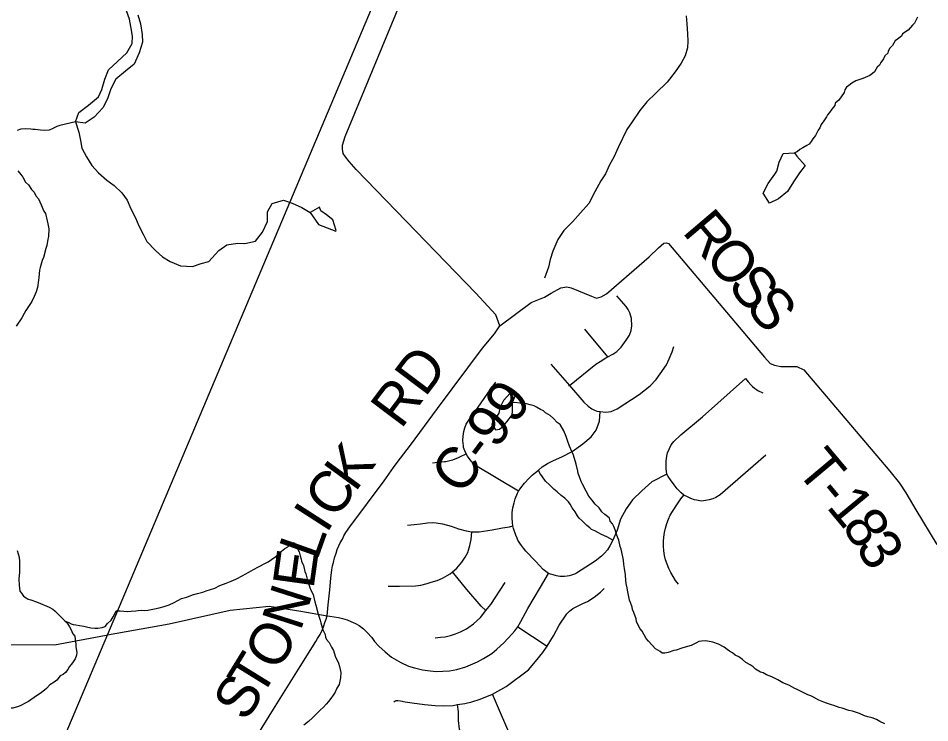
# Model space of a CAD drawing. Extents: x 0 to 34, y 0 to 22.
# Drawn here: x 8.015 to 8.641, y 16.311 to 16.795 of the extents above; entities that cross this region are included whole.
import ezdxf

# ---------------------------------------------------------------- set-up
doc = ezdxf.new("R2010")
doc.units = 0
for name, color, linetype in [('GM_X_Corporation', 7, 'Continuous'), ('GM_X_County_Road', 7, 'Continuous'), ('GM_X_County_Road_Text', 7, 'Continuous'), ('GM_X_Minor_Lake', 7, 'Continuous'), ('GM_X_Minor_River', 7, 'Continuous'), ('GM_X_Township', 7, 'Continuous'), ('GM_X_Township_Road', 7, 'Continuous'), ('GM_X_Township_Road_Text', 7, 'Continuous')]:
    doc.layers.add(name, color=color, linetype=linetype)

msp = doc.modelspace()

# ---------------------------------------------------------------- linework, layer by layer
at = {"layer": 'GM_X_Corporation'}
msp.add_lwpolyline([(8.48388, 17.33901), (8.07623, 16.37167), (8.03576, 16.27564)], dxfattribs=at)
at = {"layer": 'GM_X_County_Road'}
msp.add_line((8.19034, 16.32044), (8.2086, 16.34978), dxfattribs=at)
for points in [[(8.34554, 16.58365), (8.34282, 16.59136), (8.32915, 16.60605), (8.2471, 16.69119), (8.24218, 16.69661), (8.23968, 16.69986), (8.2381, 16.70219), (8.2376, 16.70502), (8.23768, 16.70769), (8.23951, 16.71369), (8.3129, 16.89147)], [(8.23054, 16.41746), (8.23076, 16.4188), (8.23138, 16.42121), (8.23219, 16.42433), (8.23326, 16.42763), (8.23406, 16.43004), (8.23513, 16.43254), (8.23593, 16.43459), (8.23754, 16.43727), (8.23861, 16.43941), (8.23986, 16.44164), (8.24262, 16.44556), (8.26629, 16.4772), (8.27271, 16.48647), (8.27521, 16.48977), (8.28428, 16.50168), (8.30293, 16.52684), (8.33385, 16.56838), (8.34208, 16.57812), (8.34554, 16.58365)], [(8.2271, 16.38459), (8.2277, 16.39196), (8.22898, 16.40234), (8.2296, 16.41046), (8.23031, 16.41612), (8.23054, 16.41746)], [(8.2086, 16.34978), (8.21929, 16.36697), (8.2205, 16.36889), (8.2222, 16.37174), (8.2238, 16.37522), (8.22478, 16.37772), (8.22559, 16.37986), (8.22634, 16.38222), (8.2271, 16.38459)], [(8.15853, 16.26881), (8.1597, 16.27071), (8.17295, 16.29239), (8.17469, 16.29529), (8.19034, 16.32044)]]:
    msp.add_lwpolyline(points, dxfattribs=at)
at = {"layer": 'GM_X_Minor_Lake'}
for points in [[(8.54809, 16.70243), (8.5496, 16.70026), (8.55519, 16.69389), (8.5513, 16.68883), (8.54739, 16.68263), (8.54328, 16.67605), (8.5371, 16.67102), (8.53077, 16.6679), (8.52652, 16.67482), (8.52986, 16.68141), (8.53454, 16.68779)], [(8.53454, 16.68779), (8.53591, 16.68986), (8.53735, 16.69611), (8.54012, 16.70214), (8.54809, 16.70243)], [(8.22271, 16.66264), (8.2218, 16.66513), (8.21546, 16.66163)], [(8.21546, 16.66163), (8.22122, 16.65335), (8.23312, 16.64877), (8.23332, 16.64915), (8.23097, 16.6566), (8.22657, 16.65996), (8.22271, 16.66264)], [(8.35434, 16.53086), (8.35592, 16.53525), (8.35484, 16.5385), (8.35273, 16.53739), (8.34826, 16.53234), (8.34571, 16.52744), (8.34488, 16.52366), (8.34355, 16.52157), (8.34214, 16.51933), (8.34079, 16.51822), (8.34018, 16.51595), (8.34278, 16.51229), (8.34545, 16.51262), (8.34815, 16.51505), (8.35048, 16.51786)], [(8.35048, 16.51786), (8.35368, 16.52179), (8.35401, 16.52301), (8.35423, 16.52474), (8.35434, 16.53086)]]:
    msp.add_lwpolyline(points, dxfattribs=at)
at = {"layer": 'GM_X_Minor_River'}
for points in [[(8.06324, 16.73518), (8.07, 16.74096), (8.07237, 16.74605), (8.07439, 16.75324), (8.07698, 16.75946), (8.08316, 16.76525), (8.08955, 16.77122), (8.09308, 16.77762), (8.09336, 16.78275), (8.09234, 16.78942), (8.09128, 16.79438), (8.08929, 16.80011)], [(8.09704, 16.79732), (8.09902, 16.7912), (8.10004, 16.78377), (8.10033, 16.77863), (8.09792, 16.77126), (8.09455, 16.76353), (8.08857, 16.75869), (8.082, 16.7531), (8.07865, 16.74651), (8.07625, 16.73952), (8.0731, 16.73349), (8.06709, 16.72714), (8.06093, 16.72287), (8.05429, 16.72394), (8.05668, 16.73017), (8.06324, 16.73518)], [(8.47348, 16.79663), (8.47395, 16.79111), (8.47459, 16.78425), (8.4747, 16.77931), (8.47442, 16.77456), (8.47281, 16.76927), (8.47025, 16.76418), (8.46615, 16.75817), (8.46051, 16.75105), (8.45277, 16.74358), (8.44658, 16.73761), (8.44172, 16.73161), (8.43645, 16.72391), (8.43274, 16.71846), (8.4272, 16.70658), (8.42385, 16.69961), (8.4209, 16.69434), (8.41813, 16.68812), (8.415, 16.68323), (8.41088, 16.6757), (8.40674, 16.66779), (8.40093, 16.66143), (8.39568, 16.65544), (8.38968, 16.64927), (8.38539, 16.64307), (8.38201, 16.63496), (8.3802, 16.62929), (8.37916, 16.62398), (8.37636, 16.61643)], [(8.63254, 16.79567), (8.63039, 16.79171), (8.62903, 16.79021), (8.62593, 16.78684), (8.62209, 16.78425), (8.62149, 16.78274), (8.61879, 16.7805), (8.61706, 16.77939), (8.6153, 16.77619), (8.61355, 16.77432), (8.61238, 16.77244), (8.61217, 16.77092), (8.61004, 16.76905), (8.60906, 16.76717), (8.60731, 16.76454), (8.60633, 16.76284), (8.60478, 16.76135), (8.60302, 16.75815), (8.60148, 16.75703), (8.59974, 16.75573), (8.59495, 16.75353), (8.59018, 16.7521), (8.5873, 16.75043), (8.58518, 16.74876), (8.58364, 16.74765), (8.58247, 16.74576), (8.58206, 16.74387), (8.57836, 16.7388)], [(8.57836, 16.7388), (8.57585, 16.73656), (8.57563, 16.73504), (8.57369, 16.73242), (8.57194, 16.73035), (8.57058, 16.72867), (8.56999, 16.72716), (8.56823, 16.72452), (8.56629, 16.7219), (8.5653, 16.71982), (8.56432, 16.71813), (8.56236, 16.71436), (8.56061, 16.7121), (8.55944, 16.71022), (8.55808, 16.70854), (8.55635, 16.70761), (8.55366, 16.70595), (8.55155, 16.70485), (8.54981, 16.70316), (8.54809, 16.70243)], [(8.05429, 16.72394), (8.04353, 16.72135), (8.04143, 16.72062), (8.03836, 16.71897), (8.03625, 16.71805), (8.03282, 16.71792), (8.03036, 16.71815), (8.02656, 16.7186), (8.02504, 16.71863), (8.02353, 16.71884), (8.01973, 16.71891), (8.01668, 16.71877), (8.0142, 16.71787)], [(8.05433, 16.72393), (8.05658, 16.71679), (8.05768, 16.71095), (8.05873, 16.7058), (8.06186, 16.69986), (8.06556, 16.6939), (8.07003, 16.68869), (8.07584, 16.68365), (8.08073, 16.68014), (8.08616, 16.6751), (8.08968, 16.66991), (8.09224, 16.66416), (8.09537, 16.65783), (8.09774, 16.65228), (8.10069, 16.64672), (8.10326, 16.64173), (8.10924, 16.63535), (8.11411, 16.63109), (8.11938, 16.62795), (8.12637, 16.62498), (8.13454, 16.62446), (8.14047, 16.62644), (8.14582, 16.62787), (8.15261, 16.63555), (8.1582, 16.63944), (8.16545, 16.64045), (8.17058, 16.64017), (8.17784, 16.64195), (8.1827, 16.64794), (8.18606, 16.6553), (8.18617, 16.66195), (8.18932, 16.66779), (8.19716, 16.66993), (8.20302, 16.66793), (8.20962, 16.66496), (8.21546, 16.66163)], [(8.01673, 16.68758), (8.01822, 16.68584), (8.01987, 16.68239), (8.02212, 16.68045), (8.02397, 16.67738), (8.02584, 16.67544), (8.02712, 16.67295), (8.0288, 16.67102), (8.03063, 16.6668), (8.03265, 16.66258), (8.03376, 16.66085), (8.03482, 16.65589), (8.03536, 16.65378), (8.03587, 16.65035), (8.03578, 16.64503), (8.03536, 16.64313), (8.03453, 16.63896), (8.03393, 16.63688), (8.0323, 16.63064), (8.03132, 16.62856), (8.0301, 16.62383), (8.02949, 16.62194), (8.02903, 16.617), (8.02881, 16.6151), (8.02815, 16.60998), (8.02734, 16.60695), (8.02596, 16.60374), (8.02438, 16.60053), (8.02146, 16.5964), (8.02028, 16.59414), (8.01911, 16.59207), (8.01735, 16.58925), (8.01364, 16.58342)], [(8.01468, 16.69009), (8.01673, 16.68758)], [(8.43334, 16.40206), (8.43299, 16.40377), (8.43247, 16.40683), (8.43212, 16.40874), (8.432, 16.41273), (8.43131, 16.41712), (8.43079, 16.41979), (8.43065, 16.42283), (8.43011, 16.42493), (8.42887, 16.43028), (8.42833, 16.43219), (8.42727, 16.43659), (8.42672, 16.43812), (8.42582, 16.4406), (8.42491, 16.44347), (8.424, 16.44577), (8.42308, 16.44769), (8.42141, 16.44962), (8.42106, 16.45153), (8.41956, 16.4527), (8.41768, 16.45406), (8.41562, 16.456), (8.41396, 16.45869), (8.41115, 16.46121), (8.40872, 16.4641), (8.40668, 16.46661), (8.40503, 16.47025), (8.40244, 16.47486), (8.40152, 16.47678), (8.40025, 16.48004), (8.39953, 16.48233), (8.39917, 16.48386), (8.39811, 16.48863), (8.39613, 16.49494), (8.39503, 16.49744), (8.39338, 16.50108), (8.39229, 16.50433), (8.39121, 16.50777), (8.38957, 16.5116), (8.38717, 16.51583), (8.38491, 16.51739), (8.38249, 16.5201), (8.38024, 16.52204), (8.37704, 16.52399), (8.37554, 16.52535), (8.37365, 16.52615), (8.37083, 16.52791), (8.36932, 16.52869), (8.36649, 16.5295), (8.36403, 16.53012), (8.36232, 16.53034), (8.35947, 16.53058), (8.35606, 16.53102), (8.35434, 16.53086)], [(8.04717, 16.38085), (8.04974, 16.37986), (8.05125, 16.37907), (8.05276, 16.37866), (8.05447, 16.37825), (8.05712, 16.37783), (8.05996, 16.3774), (8.06186, 16.37699), (8.06489, 16.37636), (8.06754, 16.37593), (8.06964, 16.37609), (8.07249, 16.37642), (8.0746, 16.37714), (8.07634, 16.3792), (8.07866, 16.38145), (8.08003, 16.38389), (8.08121, 16.38597), (8.08219, 16.38785), (8.08504, 16.38799), (8.08998, 16.38752), (8.09245, 16.38767), (8.09569, 16.38799), (8.0974, 16.38815), (8.09931, 16.38831), (8.10178, 16.38827), (8.10406, 16.38842), (8.10845, 16.38929), (8.11169, 16.39), (8.11513, 16.39089), (8.11857, 16.39216), (8.12202, 16.39362), (8.12701, 16.39638), (8.13063, 16.39727), (8.13465, 16.39891), (8.13809, 16.3998), (8.13981, 16.40034), (8.14172, 16.40088), (8.14402, 16.40179), (8.14688, 16.4025), (8.14994, 16.40359), (8.15339, 16.40524), (8.15779, 16.40688), (8.16123, 16.40834), (8.1643, 16.40961), (8.16621, 16.41053), (8.16775, 16.41146), (8.16928, 16.41219), (8.17082, 16.41311), (8.17332, 16.41459), (8.17639, 16.41625), (8.17984, 16.41809), (8.18463, 16.42067), (8.18655, 16.42159), (8.18886, 16.42326), (8.19194, 16.4253), (8.19348, 16.42698), (8.1958, 16.42903), (8.19792, 16.43071), (8.20003, 16.432), (8.20197, 16.43406), (8.20445, 16.43478), (8.20538, 16.43324), (8.20648, 16.43094), (8.20777, 16.42844), (8.20848, 16.42577), (8.2092, 16.42347), (8.20956, 16.42195), (8.21084, 16.41907), (8.21172, 16.41506), (8.21245, 16.41334), (8.21388, 16.4078), (8.21515, 16.40397), (8.21588, 16.40225), (8.21754, 16.39918), (8.21859, 16.39402), (8.21931, 16.39173), (8.22092, 16.38561), (8.22218, 16.3816), (8.22272, 16.37969), (8.22416, 16.37491), (8.22582, 16.37164), (8.22598, 16.36993), (8.22671, 16.36821), (8.22838, 16.36608), (8.23004, 16.36301), (8.23134, 16.36071), (8.2326, 16.35688), (8.2348, 16.35209), (8.23552, 16.34979), (8.2364, 16.3456), (8.23634, 16.34198), (8.23531, 16.33744), (8.23375, 16.3348), (8.23256, 16.33216), (8.2312, 16.33009), (8.22964, 16.32765), (8.22809, 16.32577), (8.22634, 16.3239), (8.2244, 16.32165), (8.22228, 16.31979), (8.21996, 16.31736)], [(8.01427, 16.42936), (8.01571, 16.42477), (8.01585, 16.42172), (8.01573, 16.4145), (8.01546, 16.40975), (8.01558, 16.40556), (8.01573, 16.40347), (8.01608, 16.40156), (8.0172, 16.40002), (8.01849, 16.39809), (8.02038, 16.39692), (8.02188, 16.39594), (8.02358, 16.39553), (8.02755, 16.39413), (8.03019, 16.39294), (8.03453, 16.39116), (8.03623, 16.39056), (8.03868, 16.38899), (8.04037, 16.38763), (8.04317, 16.38492), (8.04542, 16.38279), (8.04691, 16.38105), (8.04841, 16.37988), (8.05007, 16.377), (8.051, 16.37546), (8.05246, 16.3722), (8.05377, 16.37047), (8.05411, 16.36837), (8.05444, 16.36513), (8.0544, 16.36323), (8.0551, 16.35942), (8.05488, 16.35752), (8.05407, 16.35506), (8.05213, 16.35224), (8.05018, 16.3498), (8.04901, 16.34773), (8.04745, 16.34567), (8.04572, 16.34418), (8.0438, 16.34326), (8.04147, 16.34026), (8.03955, 16.33896), (8.03666, 16.33711), (8.03434, 16.33468), (8.03068, 16.33151), (8.0276, 16.32966)], [(8.60991, 16.31035), (8.60651, 16.31193), (8.60425, 16.3133), (8.60142, 16.31449), (8.59839, 16.31512), (8.59593, 16.31592), (8.59254, 16.31731), (8.58781, 16.31892), (8.58535, 16.31953), (8.58062, 16.32113), (8.57854, 16.32155), (8.57495, 16.32294), (8.57344, 16.32335), (8.56985, 16.32455), (8.56815, 16.32515), (8.56475, 16.32655), (8.56098, 16.3287), (8.5591, 16.3295), (8.55702, 16.33029), (8.55306, 16.33226), (8.54985, 16.33384), (8.54816, 16.33463), (8.54401, 16.33699), (8.53986, 16.33839), (8.53647, 16.34054), (8.53252, 16.3427), (8.52873, 16.34391), (8.52648, 16.34528), (8.52459, 16.34588), (8.5212, 16.34784), (8.5197, 16.34939), (8.51745, 16.35095), (8.51462, 16.35252), (8.51237, 16.35446), (8.50975, 16.35641), (8.50729, 16.3576), (8.50542, 16.35915), (8.50335, 16.36014), (8.50185, 16.36149), (8.49959, 16.36306), (8.49582, 16.36502), (8.49186, 16.36642), (8.48825, 16.36706), (8.48655, 16.36728), (8.48407, 16.36713), (8.48236, 16.36678), (8.48063, 16.36605), (8.47699, 16.36421), (8.47279, 16.36295), (8.47069, 16.36223), (8.46667, 16.36097), (8.46515, 16.36061), (8.46113, 16.35935), (8.45884, 16.35882), (8.45713, 16.35885), (8.45563, 16.36002), (8.45262, 16.36178), (8.44776, 16.367), (8.44609, 16.36893), (8.44332, 16.37393), (8.44202, 16.37566), (8.43944, 16.38046), (8.43928, 16.38237), (8.43764, 16.38677), (8.43673, 16.38888), (8.43656, 16.3904), (8.43529, 16.39366), (8.43475, 16.39538), (8.43404, 16.39881), (8.43334, 16.40206)], [(8.0276, 16.32966), (8.02202, 16.32557), (8.02011, 16.32466), (8.01665, 16.32281), (8.01512, 16.32227), (8.0113, 16.3212), (8.00921, 16.32104), (8.00673, 16.32071), (8.00388, 16.32057), (7.99931, 16.31988), (7.9955, 16.31957), (7.99226, 16.31906), (7.98978, 16.31853), (7.98691, 16.31782), (7.98385, 16.31635), (7.97907, 16.31472), (7.97446, 16.31195), (7.97101, 16.31049)], [(8.21996, 16.31736), (8.21706, 16.31456), (8.21416, 16.31194), (8.21108, 16.30934)]]:
    msp.add_lwpolyline(points, dxfattribs=at)
at = {"layer": 'GM_X_Township'}
msp.add_lwpolyline([(8.48388, 17.33901), (8.07623, 16.37167), (8.03576, 16.27564)], dxfattribs=at)
at = {"layer": 'GM_X_Township_Road'}
for p, q in [((8.41983, 16.56249), (8.40391, 16.58151)), ((8.38074, 16.55732), (8.39343, 16.54278)), ((8.35795, 16.37694), (8.37805, 16.36367)), ((8.36068, 16.28436), (8.34057, 16.33069))]:
    msp.add_line(p, q, dxfattribs=at)
for points in [[(8.34554, 16.58365), (8.36723, 16.59974), (8.37642, 16.60337), (8.3808, 16.60606), (8.38764, 16.60973), (8.39158, 16.61048), (8.39457, 16.60978), (8.40864, 16.60399), (8.41196, 16.60274), (8.41527, 16.60357), (8.41899, 16.60564), (8.44812, 16.63117), (8.45459, 16.63723), (8.45831, 16.64046), (8.45976, 16.64078), (8.4614, 16.64031), (8.52747, 16.56217), (8.53119, 16.55782), (8.5343, 16.55658), (8.53854, 16.55575), (8.54361, 16.55575), (8.54961, 16.55586), (8.55438, 16.55347), (8.55686, 16.55047), (8.61348, 16.48382), (8.6201, 16.47554), (8.62445, 16.46891), (8.63118, 16.45722), (8.64577, 16.43341)], [(8.41983, 16.56249), (8.42326, 16.5642), (8.42599, 16.56609), (8.42897, 16.56898), (8.43247, 16.57378), (8.43463, 16.5774), (8.43575, 16.58053), (8.4363, 16.5838), (8.43604, 16.58877), (8.43483, 16.59274), (8.43371, 16.59497), (8.43229, 16.59702), (8.42608, 16.60428)], [(8.41452, 16.52481), (8.41839, 16.52435), (8.42212, 16.52492), (8.42619, 16.52661), (8.44123, 16.53656), (8.44892, 16.54244), (8.45288, 16.54685), (8.45582, 16.5507), (8.46, 16.55692), (8.46193, 16.56099), (8.46407, 16.56596), (8.46521, 16.56947)], [(8.39311, 16.54253), (8.39343, 16.54278), (8.41149, 16.55733), (8.41446, 16.55932), (8.41848, 16.56172), (8.41983, 16.56249)], [(8.3225, 16.49571), (8.32154, 16.49792), (8.32079, 16.50022), (8.32062, 16.50122), (8.32028, 16.50487), (8.32036, 16.50791), (8.32086, 16.5112), (8.32152, 16.51374), (8.32258, 16.51621), (8.32431, 16.51901), (8.32554, 16.52065), (8.32867, 16.52492), (8.335, 16.5338), (8.33911, 16.53964), (8.34289, 16.54506)], [(8.39343, 16.54278), (8.40338, 16.53137), (8.40625, 16.52843), (8.40878, 16.52661), (8.41025, 16.52593), (8.41217, 16.52514), (8.41452, 16.52481)], [(8.52829, 16.4949), (8.49685, 16.4676), (8.49401, 16.46583), (8.49188, 16.46488), (8.48928, 16.46417), (8.4868, 16.4637), (8.48408, 16.46335), (8.48066, 16.46394), (8.47936, 16.46429), (8.47676, 16.46512), (8.47451, 16.46618), (8.47203, 16.46748), (8.47026, 16.4689), (8.46742, 16.47174), (8.46529, 16.47457), (8.46281, 16.478), (8.46115, 16.48013), (8.46042, 16.4819), (8.45985, 16.4858), (8.45985, 16.49088), (8.46021, 16.49419), (8.46068, 16.49644), (8.46222, 16.49951), (8.46328, 16.50188), (8.46517, 16.50424), (8.47002, 16.50885), (8.48491, 16.52126), (8.51432, 16.54743)], [(8.51432, 16.54743), (8.5162, 16.5453), (8.51809, 16.54317), (8.51866, 16.54257), (8.51923, 16.54198), (8.52047, 16.54089), (8.52181, 16.53992), (8.52212, 16.53973), (8.52322, 16.53907), (8.52625, 16.53776)], [(8.46042, 16.4819), (8.45011, 16.47658), (8.44312, 16.47043), (8.43664, 16.46427), (8.43231, 16.45795), (8.42849, 16.4508), (8.42616, 16.44332), (8.42326, 16.43653), (8.42127, 16.43258), (8.4195, 16.42987), (8.41756, 16.42755), (8.41726, 16.42723), (8.41552, 16.42539), (8.41104, 16.42196), (8.39821, 16.41383), (8.39683, 16.41306), (8.39495, 16.41245), (8.39318, 16.41201), (8.39185, 16.41173), (8.39013, 16.41151), (8.38842, 16.41151), (8.38674, 16.41162), (8.38447, 16.41207), (8.38237, 16.41256), (8.38043, 16.41317), (8.379, 16.41361), (8.37535, 16.41643), (8.37037, 16.4218), (8.36357, 16.42893), (8.3618, 16.43092), (8.36047, 16.43275), (8.35931, 16.43441), (8.35809, 16.43651), (8.35744, 16.43792), (8.35656, 16.43997), (8.355, 16.44455), (8.35456, 16.44633), (8.35434, 16.44865), (8.35412, 16.45169), (8.35418, 16.4555), (8.35456, 16.4586), (8.35539, 16.46209), (8.35622, 16.46494), (8.35777, 16.4687), (8.35855, 16.47008), (8.3601, 16.47233), (8.36267, 16.47561), (8.36555, 16.4788), (8.36792, 16.48104), (8.37014, 16.48292), (8.37213, 16.48457), (8.37482, 16.48676), (8.37843, 16.48906), (8.38209, 16.49088), (8.38874, 16.49388), (8.39539, 16.49737), (8.40255, 16.50269), (8.40837, 16.50751), (8.41169, 16.512), (8.41419, 16.51816), (8.41452, 16.52481)], [(8.29952, 16.48961), (8.30468, 16.49022), (8.30755, 16.4905), (8.30851, 16.49063), (8.30948, 16.49076), (8.31138, 16.49114), (8.31232, 16.4914), (8.31326, 16.49166), (8.31509, 16.49231), (8.31688, 16.49307), (8.31867, 16.49391), (8.3225, 16.49571)], [(8.35855, 16.47008), (8.32896, 16.48779), (8.32588, 16.49077), (8.32334, 16.49421), (8.3225, 16.49571)], [(8.42326, 16.43653), (8.41918, 16.43883), (8.41552, 16.44033), (8.41302, 16.44166), (8.41086, 16.44282), (8.4087, 16.44382), (8.40737, 16.44498), (8.40537, 16.44648), (8.40371, 16.44814), (8.40221, 16.44981), (8.40022, 16.45163), (8.39905, 16.4533), (8.39739, 16.45596), (8.39539, 16.45879), (8.3939, 16.46111), (8.39273, 16.46278), (8.3914, 16.46411), (8.39024, 16.46527), (8.38774, 16.46727), (8.38508, 16.4696), (8.38276, 16.47142), (8.37976, 16.47442), (8.3771, 16.47708), (8.37494, 16.48007), (8.37311, 16.4824), (8.37213, 16.48457)], [(8.46411, 16.45614), (8.46754, 16.46145), (8.4699, 16.46476), (8.47203, 16.46748)], [(8.46834, 16.40636), (8.46636, 16.40883), (8.46458, 16.41144), (8.46299, 16.41417), (8.46161, 16.41701), (8.46044, 16.41994), (8.45949, 16.42296), (8.45877, 16.42604), (8.45828, 16.42916), (8.45802, 16.43231), (8.458, 16.43546), (8.45821, 16.43862), (8.45865, 16.44175), (8.45933, 16.44483), (8.46023, 16.44786), (8.46135, 16.45081), (8.46269, 16.45368), (8.46411, 16.45614)], [(8.28236, 16.44679), (8.28678, 16.44721), (8.2912, 16.44776), (8.29589, 16.44831), (8.29921, 16.44859), (8.30197, 16.44831), (8.30639, 16.44762), (8.31218, 16.4461), (8.31716, 16.44417), (8.32254, 16.44279), (8.32641, 16.4421), (8.33138, 16.44224), (8.34049, 16.44348), (8.34739, 16.44486), (8.35222, 16.44569), (8.35456, 16.44633)], [(8.26897, 16.40496), (8.27684, 16.40482), (8.28775, 16.4051), (8.29148, 16.40565), (8.29576, 16.40662), (8.29852, 16.40758), (8.30252, 16.40869), (8.30639, 16.41048), (8.30956, 16.41228), (8.31149, 16.41338), (8.31315, 16.41462), (8.31605, 16.41725), (8.31964, 16.42139), (8.32185, 16.4247), (8.32364, 16.42802), (8.32502, 16.43285), (8.32599, 16.43699), (8.32641, 16.4421)], [(8.2271, 16.38459), (8.22891, 16.38436), (8.23491, 16.38327), (8.23756, 16.38271), (8.24077, 16.38168), (8.24343, 16.38072), (8.2465, 16.37935), (8.24909, 16.37785), (8.25198, 16.37553), (8.25466, 16.37315), (8.2577, 16.36968), (8.25965, 16.36678), (8.2626, 16.36368), (8.2668, 16.35978), (8.27137, 16.35622), (8.27766, 16.35246), (8.28285, 16.35002), (8.28697, 16.34872), (8.29254, 16.34735), (8.29789, 16.34662), (8.30201, 16.34633), (8.30642, 16.34641), (8.31105, 16.34677), (8.31604, 16.34771), (8.32241, 16.34959), (8.33029, 16.35291), (8.33447, 16.35509), (8.34007, 16.35867), (8.34366, 16.36152), (8.34829, 16.36594), (8.35404, 16.37204), (8.35601, 16.37432), (8.35795, 16.37694), (8.36002, 16.38051), (8.36493, 16.38954), (8.37353, 16.4043), (8.379, 16.41361)], [(8.33607, 16.38825), (8.33276, 16.39115), (8.32309, 16.40261), (8.31315, 16.41462)], [(8.30114, 16.36948), (8.30501, 16.36975), (8.30818, 16.37017), (8.31177, 16.371), (8.31522, 16.37224), (8.31854, 16.37362), (8.32268, 16.37569), (8.32765, 16.379), (8.33234, 16.38328), (8.33607, 16.38825), (8.33952, 16.3924), (8.34932, 16.40731)], [(8.37805, 16.36367), (8.3826, 16.37072), (8.38646, 16.37804), (8.38784, 16.38025), (8.38978, 16.38315), (8.39157, 16.38591), (8.3935, 16.3877), (8.39585, 16.3895), (8.39985, 16.39171), (8.40262, 16.39309), (8.40593, 16.39433), (8.41049, 16.39737), (8.41477, 16.40082), (8.41725, 16.4033)], [(8.07536, 16.37123), (8.07634, 16.37141), (8.11862, 16.37909), (8.16041, 16.38842), (8.18734, 16.39118), (8.2091, 16.38773), (8.2271, 16.38459)], [(7.89449, 16.34801), (7.92419, 16.36045), (7.94526, 16.36493), (7.96805, 16.36493), (7.99948, 16.36493), (8.03988, 16.36459), (8.07536, 16.37123)], [(8.34057, 16.33069), (8.35007, 16.33595), (8.36534, 16.34753), (8.37017, 16.35319), (8.37528, 16.3594), (8.37805, 16.36367)], [(8.31655, 16.32352), (8.3215, 16.32436), (8.32641, 16.32551), (8.3322, 16.32732), (8.34057, 16.33069)], [(8.27286, 16.32545), (8.27364, 16.32594), (8.27447, 16.32627), (8.27566, 16.32639), (8.27755, 16.32613), (8.28057, 16.32542), (8.28545, 16.32475), (8.29386, 16.32371), (8.30134, 16.32288), (8.30678, 16.32265), (8.31366, 16.32303), (8.31655, 16.32352)], [(8.32538, 16.29119), (8.32442, 16.29232), (8.3219, 16.29681), (8.32042, 16.30056), (8.31805, 16.30672), (8.31726, 16.31254), (8.31724, 16.31867), (8.31655, 16.32352)]]:
    msp.add_lwpolyline(points, dxfattribs=at)

# ---------------------------------------------------------------- texts
at = {"layer": 'GM_X_County_Road_Text'}
for s, height, rotation, p in [('RD', 0.028409, 53.03133, (8.27778, 16.51214)), ('C-99', 0.028409, 53.26709, (8.31917, 16.46631)), ('K', 0.02841, 53.92789, (8.24629, 16.46887)), ('C', 0.02841, 54.20189, (8.23266, 16.44997)), ('I', 0.02841, 57.27555, (8.22658, 16.44049)), ('L', 0.02841, 70.44418, (8.22023, 16.42201)), ('E', 0.02841, 82.06207, (8.21766, 16.40244)), ('N', 0.02841, 72.20289, (8.20883, 16.37344)), ('O', 0.02841, 58.48445, (8.19267, 16.34539)), ('T', 0.02841, 58.30714, (8.18145, 16.32723)), ('S', 0.02841, 58.30689, (8.17138, 16.31092))]:
    msp.add_text(s, height=height, rotation=rotation, dxfattribs=at).set_placement(p)
at = {"layer": 'GM_X_Township_Road_Text'}
for s, rotation, p in [('R', 310.3528, (8.47028, 16.64806)), ('O', 309.81537, (8.48534, 16.63033)), ('S', 309.80558, (8.50135, 16.61113)), ('S', 309.80558, (8.51362, 16.59641)), ('T', 309.96634, (8.5482, 16.48443)), ('-', 309.91551, (8.56185, 16.46814)), ('1', 309.62701, (8.56931, 16.45922)), ('8', 303.02758, (8.57996, 16.44644)), ('3', 301.71524, (8.58941, 16.43192))]:
    msp.add_text(s, height=0.02841, rotation=rotation, dxfattribs=at).set_placement(p)

doc.saveas('drawing.dxf')
